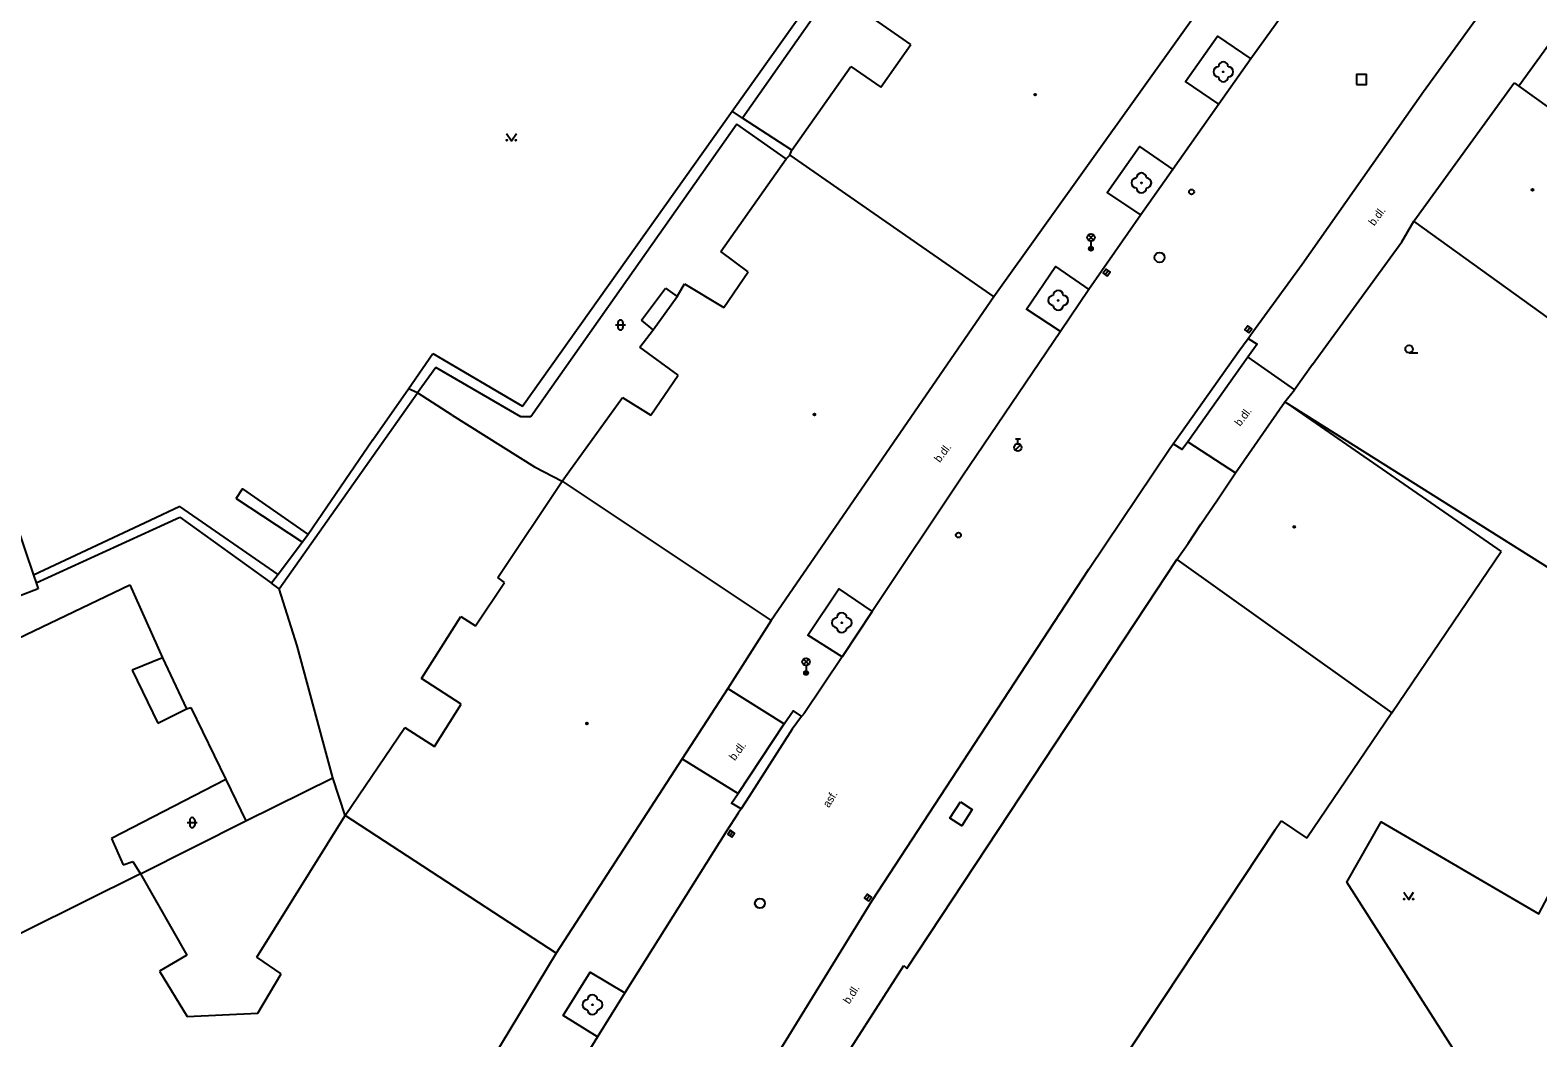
# Model space of a CAD drawing. Extents: x -599770 to -598493, y -1162076 to -1159209.
# Drawn here: x -599223.2 to -599147.3, y -1161484.3 to -1161433.6 of the extents above; entities that cross this region are included whole.
import ezdxf

# ---------------------------------------------------------------- set-up
doc = ezdxf.new("R2010")
doc.units = 0
doc.layers.add('Podklad', color=7, linetype='Continuous')

msp = doc.modelspace()

# ---------------------------------------------------------------- linework, layer by layer
at = {"layer": 'Podklad'}
for p, q in [((-599169.913, -1161444.16), (-599169.648, -1161443.895)), ((-599169.913, -1161443.895), (-599169.648, -1161444.16)), ((-599169.78, -1161444.215), (-599169.78, -1161444.59)), ((-599169.062, -1161445.892), (-599168.918, -1161445.688)), ((-599193.713, -1161448.428), (-599193.213, -1161448.428)), ((-599193.588, -1161448.303), (-599193.588, -1161448.553)), ((-599193.338, -1161448.303), (-599193.338, -1161448.553)), ((-599161.932, -1161448.752), (-599161.788, -1161448.548)), ((-599153.77, -1161449.828), (-599153.332, -1161449.828)), ((-599173.585, -1161454.152), (-599173.335, -1161454.152)), ((-599173.46, -1161454.402), (-599173.46, -1161454.152)), ((-599173.589, -1161454.726), (-599173.324, -1161454.461)), ((-599184.253, -1161465.51), (-599183.988, -1161465.245)), ((-599184.253, -1161465.245), (-599183.988, -1161465.51)), ((-599184.12, -1161465.565), (-599184.12, -1161465.94)), ((-599215.263, -1161473.468), (-599214.763, -1161473.468)), ((-599215.138, -1161473.343), (-599215.138, -1161473.593)), ((-599214.888, -1161473.343), (-599214.888, -1161473.593)), ((-599187.962, -1161474.132), (-599187.818, -1161473.928)), ((-599181.072, -1161477.342), (-599180.928, -1161477.138))]:
    msp.add_line(p, q, dxfattribs=at)
for points in [[(-599187.84, -1161437.67), (-599175.96, -1161420.96)], [(-599175.51, -1161421.2), (-599187.32, -1161438.02)], [(-599152.29, -1161421.88), (-599152.71, -1161422.51), (-599161.73, -1161435.03)], [(-599161.87, -1161449.1), (-599161.64, -1161448.77), (-599159.15, -1161445.36), (-599153.05, -1161436.68), (-599148.97, -1161431.05), (-599145.91, -1161426.98), (-599145.22, -1161426.08)], [(-599162.59, -1161430.1), (-599174.67, -1161447.02)], [(-599178.84, -1161434.31), (-599180.87, -1161432.91)], [(-599180.36, -1161436.46), (-599178.84, -1161434.31)], [(-599163.35, -1161437.31), (-599165.03, -1161436.17), (-599163.42, -1161433.9), (-599161.73, -1161435.03)], [(-599146.75, -1161434.34), (-599148.25, -1161436.41)], [(-599161.73, -1161435.03), (-599163.35, -1161437.31)], [(-599184.84, -1161439.64), (-599181.87, -1161435.43)], [(-599181.87, -1161435.43), (-599180.36, -1161436.46)], [(-599153.53, -1161443.2), (-599148.48, -1161436.25)], [(-599148.48, -1161436.25), (-599148.25, -1161436.41), (-599144.51, -1161439.09)], [(-599163.35, -1161437.31), (-599165.66, -1161440.6)], [(-599198.39, -1161452.52), (-599187.84, -1161437.67)], [(-599187.32, -1161438.02), (-599187.84, -1161437.67)], [(-599184.84, -1161439.64), (-599187.32, -1161438.02)], [(-599199.2, -1161438.785), (-599198.95, -1161439.16), (-599198.7, -1161438.785)], [(-599187.6, -1161438.33), (-599197.97, -1161453.05)], [(-599185.12, -1161440.07), (-599187.6, -1161438.33)], [(-599184.93, -1161439.89), (-599184.84, -1161439.64)], [(-599167.27, -1161442.88), (-599168.97, -1161441.76), (-599167.33, -1161439.45), (-599165.66, -1161440.6)], [(-599188.41, -1161444.73), (-599185.12, -1161440.07)], [(-599185.12, -1161440.07), (-599184.93, -1161439.89)], [(-599184.93, -1161439.89), (-599174.67, -1161447.02)], [(-599165.66, -1161440.6), (-599167.27, -1161442.88)], [(-599167.27, -1161442.88), (-599169.88, -1161446.65)], [(-599158.63, -1161450.42), (-599156.3, -1161447.21), (-599154.14, -1161444.24), (-599153.53, -1161443.2)], [(-599131.37, -1161459.16), (-599153.53, -1161443.2)], [(-599187.03, -1161445.76), (-599188.41, -1161444.73)], [(-599188.26, -1161447.55), (-599187.03, -1161445.76)], [(-599171.31, -1161448.76), (-599173.03, -1161447.63), (-599171.56, -1161445.49), (-599169.88, -1161446.65)], [(-599192.4, -1161448.19), (-599191.2, -1161446.57)], [(-599191.2, -1161446.57), (-599190.61, -1161447)], [(-599190.61, -1161447), (-599190.23, -1161446.36)], [(-599190.23, -1161446.36), (-599188.26, -1161447.55)], [(-599191.81, -1161448.67), (-599190.61, -1161447)], [(-599174.67, -1161447.02), (-599185.87, -1161463.29)], [(-599169.88, -1161446.65), (-599171.31, -1161448.76)], [(-599192.49, -1161449.54), (-599191.81, -1161448.67)], [(-599191.81, -1161448.67), (-599192.4, -1161448.19)], [(-599171.31, -1161448.76), (-599176.24, -1161456.04), (-599180.79, -1161462.84)], [(-599190.55, -1161450.95), (-599192.49, -1161449.54)], [(-599165.64, -1161454.41), (-599165.23, -1161453.82), (-599162.34, -1161449.75), (-599161.87, -1161449.1)], [(-599161.87, -1161449.1), (-599161.42, -1161449.4), (-599161.89, -1161450.04)], [(-599204.12, -1161451.64), (-599202.9, -1161449.87)], [(-599202.9, -1161449.87), (-599198.39, -1161452.52)], [(-599161.89, -1161450.04), (-599164.91, -1161454.3)], [(-599161.89, -1161450.04), (-599159.53, -1161451.69)], [(-599202.75, -1161450.57), (-599203.68, -1161451.84)], [(-599198.48, -1161453.05), (-599202.75, -1161450.57)], [(-599191.94, -1161452.96), (-599190.55, -1161450.95)], [(-599158.63, -1161450.42), (-599159.53, -1161451.69)], [(-599210.64, -1161461.7), (-599203.68, -1161451.84)], [(-599205.93, -1161454.2), (-599204.12, -1161451.64)], [(-599203.68, -1161451.84), (-599204.12, -1161451.64)], [(-599201.93, -1161452.97), (-599203.68, -1161451.84)], [(-599160.03, -1161452.29), (-599159.53, -1161451.69)], [(-599195.97, -1161455.7), (-599193.36, -1161452.07)], [(-599193.36, -1161452.07), (-599191.94, -1161452.96)], [(-599162.5, -1161455.86), (-599160.03, -1161452.29)], [(-599160.03, -1161452.29), (-599149.14, -1161459.83)], [(-599160.03, -1161452.29), (-599136.86, -1161466.87)], [(-599201.93, -1161452.97), (-599197.78, -1161455.56)], [(-599197.97, -1161453.05), (-599198.48, -1161453.05)], [(-599205.93, -1161454.2), (-599209.17, -1161458.97)], [(-599191.37, -1161494.54), (-599180.8, -1161477.39), (-599169.88, -1161460.72), (-599165.81, -1161454.65), (-599165.64, -1161454.41)], [(-599164.91, -1161454.3), (-599165.19, -1161454.7), (-599165.64, -1161454.41)], [(-599164.91, -1161454.3), (-599162.5, -1161455.86)], [(-599197.78, -1161455.56), (-599196.4, -1161456.29)], [(-599196.4, -1161456.29), (-599195.97, -1161455.7)], [(-599199.63, -1161461.14), (-599196.4, -1161456.29)], [(-599196.4, -1161456.29), (-599185.87, -1161463.29)], [(-599163.42, -1161457.22), (-599162.5, -1161455.86)], [(-599212.81, -1161457.16), (-599212.49, -1161456.68), (-599209.17, -1161458.97)], [(-599212.81, -1161457.16), (-599209.46, -1161459.36)], [(-599164.25, -1161458.45), (-599163.42, -1161457.22)], [(-599215.64, -1161457.56), (-599217.13, -1161458.26)], [(-599210.69, -1161460.98), (-599215.64, -1161457.56)], [(-599223.87, -1161458.43), (-599223, -1161461.02)], [(-599217.13, -1161458.26), (-599223, -1161461.02)], [(-599222.87, -1161461.41), (-599216.99, -1161458.72)], [(-599216.99, -1161458.72), (-599215.63, -1161458.1)], [(-599215.63, -1161458.1), (-599211.03, -1161461.42)], [(-599164.89, -1161459.42), (-599164.25, -1161458.45)], [(-599209.17, -1161458.97), (-599209.46, -1161459.36), (-599210.69, -1161460.98)], [(-599165.46, -1161460.23), (-599164.89, -1161459.42)], [(-599166.98, -1161462.55), (-599165.46, -1161460.23)], [(-599165.46, -1161460.23), (-599154.64, -1161467.94)], [(-599154.64, -1161467.94), (-599149.14, -1161459.83)], [(-599210.69, -1161460.98), (-599211.03, -1161461.42)], [(-599222.77, -1161461.7), (-599224.7, -1161462.45)], [(-599223.79, -1161464.2), (-599218.15, -1161461.5)], [(-599223, -1161461.02), (-599222.87, -1161461.41)], [(-599222.87, -1161461.41), (-599222.77, -1161461.7)], [(-599218.15, -1161461.5), (-599216.51, -1161465.17)], [(-599210.64, -1161461.7), (-599211.03, -1161461.42)], [(-599209.74, -1161464.58), (-599210.64, -1161461.7)], [(-599200.75, -1161463.57), (-599199.29, -1161461.38)], [(-599199.29, -1161461.38), (-599199.63, -1161461.14)], [(-599182.31, -1161465.13), (-599184.03, -1161464.03), (-599182.47, -1161461.71), (-599180.79, -1161462.84)], [(-599203.47, -1161466.21), (-599201.49, -1161463.09)], [(-599201.49, -1161463.09), (-599200.75, -1161463.57)], [(-599185.87, -1161463.29), (-599188.05, -1161466.72)], [(-599180.79, -1161462.84), (-599182.31, -1161465.13)], [(-599179.05, -1161480.81), (-599166.98, -1161462.55)], [(-599207.94, -1161471.21), (-599209.74, -1161464.58)], [(-599216.51, -1161465.17), (-599218.04, -1161465.8)], [(-599216.51, -1161465.17), (-599215.3, -1161467.75)], [(-599182.31, -1161465.13), (-599184.22, -1161467.98), (-599184.35, -1161468.13)], [(-599218.04, -1161465.8), (-599216.75, -1161468.47)], [(-599201.48, -1161467.5), (-599203.47, -1161466.21)], [(-599188.05, -1161466.72), (-599190.36, -1161470.26)], [(-599188.05, -1161466.72), (-599185.22, -1161468.5)], [(-599216.75, -1161468.47), (-599215.3, -1161467.75)], [(-599215.3, -1161467.75), (-599215.09, -1161467.68)], [(-599215.09, -1161467.68), (-599213.32, -1161471.3)], [(-599202.82, -1161469.63), (-599201.48, -1161467.5)], [(-599187.53, -1161472), (-599185.22, -1161468.5)], [(-599184.35, -1161468.13), (-599184.82, -1161468.77), (-599186.99, -1161472.15), (-599187.39, -1161472.77)], [(-599185.22, -1161468.5), (-599184.77, -1161467.85), (-599184.35, -1161468.13)], [(-599154.64, -1161467.94), (-599158.91, -1161474.25)], [(-599207.31, -1161473.11), (-599204.32, -1161468.68)], [(-599204.32, -1161468.68), (-599202.82, -1161469.63)], [(-599190.36, -1161470.26), (-599196.69, -1161480.03)], [(-599190.36, -1161470.26), (-599187.53, -1161472)], [(-599213.32, -1161471.3), (-599219.07, -1161474.26)], [(-599213.32, -1161471.3), (-599212.31, -1161473.38)], [(-599212.31, -1161473.38), (-599207.94, -1161471.21)], [(-599207.31, -1161473.11), (-599207.94, -1161471.21)], [(-599187.39, -1161472.77), (-599187.88, -1161472.49), (-599187.53, -1161472)], [(-599211.76, -1161480.23), (-599207.31, -1161473.11)], [(-599196.69, -1161480.03), (-599207.31, -1161473.11)], [(-599187.39, -1161472.77), (-599187.54, -1161473), (-599188.13, -1161473.89), (-599193.24, -1161482.04)], [(-599176.34, -1161472.42), (-599175.76, -1161472.81), (-599176.28, -1161473.63), (-599176.89, -1161473.25), (-599176.34, -1161472.42)], [(-599217.62, -1161476.05), (-599212.31, -1161473.38)], [(-599144.86, -1161473.56), (-599141.55, -1161475.68), (-599150.94, -1161513.38), (-599144.46, -1161515.5), (-599145.65, -1161520), (-599147.9, -1161521.32), (-599149.89, -1161521.98), (-599153.32, -1161522.38), (-599155.57, -1161521.59), (-599177.4, -1161507.96), (-599169.99, -1161493.94), (-599167.88, -1161494.47), (-599163.38, -1161497.91), (-599150.81, -1161486), (-599156.9, -1161476.47), (-599155.18, -1161473.43), (-599147.24, -1161478.06), (-599144.86, -1161473.56)], [(-599160.52, -1161473.85), (-599169.34, -1161487.15)], [(-599160.52, -1161473.85), (-599160.2, -1161473.38)], [(-599160.2, -1161473.38), (-599158.91, -1161474.25)], [(-599219.07, -1161474.26), (-599218.49, -1161475.59)], [(-599218.49, -1161475.59), (-599218, -1161475.43)], [(-599218, -1161475.43), (-599217.62, -1161476.05)], [(-599217.62, -1161476.05), (-599229.21, -1161481.79)], [(-599217.62, -1161476.05), (-599215.29, -1161480.14)], [(-599154.04, -1161476.965), (-599153.79, -1161477.34), (-599153.54, -1161476.965)], [(-599215.29, -1161480.14), (-599216.66, -1161480.95)], [(-599210.54, -1161481.07), (-599211.76, -1161480.23)], [(-599196.69, -1161480.03), (-599208.31, -1161499.24)], [(-599183.01, -1161486.59), (-599179.2, -1161480.66)], [(-599179.2, -1161480.66), (-599179.05, -1161480.81)], [(-599216.66, -1161480.95), (-599215.26, -1161483.22)], [(-599211.71, -1161483.05), (-599210.54, -1161481.07)], [(-599194.61, -1161484.25), (-599196.34, -1161483.18), (-599194.98, -1161480.99), (-599193.24, -1161482.04)], [(-599193.24, -1161482.04), (-599194.61, -1161484.25)], [(-599215.26, -1161483.22), (-599211.71, -1161483.05)], [(-599194.61, -1161484.25), (-599196.83, -1161487.83)]]:
    msp.add_lwpolyline(points, dxfattribs=at)
for points in [[(-599156.42, -1161436.33), (-599155.92, -1161436.33), (-599155.92, -1161435.83), (-599156.42, -1161435.83)], [(-599168.961, -1161445.964), (-599168.816, -1161445.761), (-599169.019, -1161445.616), (-599169.164, -1161445.819)], [(-599161.831, -1161448.824), (-599161.686, -1161448.621), (-599161.889, -1161448.476), (-599162.034, -1161448.679)], [(-599187.861, -1161474.204), (-599187.716, -1161474.001), (-599187.919, -1161473.856), (-599188.064, -1161474.059)], [(-599180.971, -1161477.414), (-599180.826, -1161477.211), (-599181.029, -1161477.066), (-599181.174, -1161477.269)]]:
    msp.add_lwpolyline(points, close=True, dxfattribs=at)
for centre, radius in [((-599163.12, -1161435.69), 0.025), ((-599172.59, -1161436.84), 0.045), ((-599172.59, -1161436.84), 0.0199), ((-599199.175, -1161439.135), 0.025), ((-599198.725, -1161439.135), 0.025), ((-599167.24, -1161441.28), 0.025), ((-599164.72, -1161441.73), 0.125), ((-599147.56, -1161441.63), 0.045), ((-599147.56, -1161441.63), 0.0199), ((-599169.78, -1161444.027), 0.188), ((-599169.78, -1161444.59), 0.1), ((-599169.78, -1161444.59), 0.0723), ((-599169.78, -1161444.59), 0.0438), ((-599166.33, -1161445.03), 0.25), ((-599171.43, -1161447.19), 0.025), ((-599153.77, -1161449.64), 0.188), ((-599183.7, -1161452.93), 0.045), ((-599183.7, -1161452.93), 0.0199), ((-599173.46, -1161454.59), 0.188), ((-599159.55, -1161458.59), 0.045), ((-599159.55, -1161458.59), 0.0199), ((-599176.45, -1161459), 0.125), ((-599182.32, -1161463.41), 0.025), ((-599184.12, -1161465.378), 0.188), ((-599184.12, -1161465.94), 0.1), ((-599184.12, -1161465.94), 0.0723), ((-599184.12, -1161465.94), 0.0438), ((-599195.15, -1161468.48), 0.045), ((-599195.15, -1161468.48), 0.0199), ((-599186.44, -1161477.53), 0.25), ((-599154.015, -1161477.315), 0.025), ((-599153.565, -1161477.315), 0.025), ((-599194.87, -1161482.63), 0.025)]:
    msp.add_circle(centre, radius, dxfattribs=at)
for centre, radius, start, end in [((-599163.12, -1161435.44), 0.25, 0, 180), ((-599163.37, -1161435.69), 0.25, 90, 270), ((-599163.12, -1161435.94), 0.25, 180, 0), ((-599162.87, -1161435.69), 0.25, 270, 90), ((-599167.49, -1161441.28), 0.25, 90, 270), ((-599167.24, -1161441.03), 0.25, 0, 180), ((-599166.99, -1161441.28), 0.25, 270, 90), ((-599167.24, -1161441.53), 0.25, 180, 0), ((-599171.68, -1161447.19), 0.25, 90, 270), ((-599171.43, -1161446.94), 0.25, 0, 180), ((-599171.18, -1161447.19), 0.25, 270, 90), ((-599171.43, -1161447.44), 0.25, 180, 0), ((-599193.463, -1161448.303), 0.125, 0, 180), ((-599193.463, -1161448.553), 0.125, 180, 0), ((-599182.57, -1161463.41), 0.25, 90, 270), ((-599182.32, -1161463.16), 0.25, 0, 180), ((-599182.07, -1161463.41), 0.25, 270, 90), ((-599182.32, -1161463.66), 0.25, 180, 0), ((-599215.013, -1161473.343), 0.125, 0, 180), ((-599215.013, -1161473.593), 0.125, 180, 0), ((-599194.87, -1161482.38), 0.25, 0, 180), ((-599195.12, -1161482.63), 0.25, 90, 270), ((-599194.87, -1161482.88), 0.25, 180, 0), ((-599194.62, -1161482.63), 0.25, 270, 90)]:
    msp.add_arc(centre, radius, start, end, dxfattribs=at)

# ---------------------------------------------------------------- texts
for s, rotation, p in [('b.dl.', 53.14, (-599155.53, -1161443.47)), ('b.dl.', 53.14, (-599162.27, -1161453.56)), ('b.dl.', 53.14, (-599177.39, -1161455.38)), ('b.dl.', 53.14, (-599187.71, -1161470.38)), ('asf.', 58.09, (-599182.971, -1161472.75)), ('b.dl.', 56.95, (-599181.95, -1161482.63))]:
    msp.add_text(s, height=0.4, rotation=rotation, dxfattribs=at).set_placement(p)

doc.saveas('drawing.dxf')
